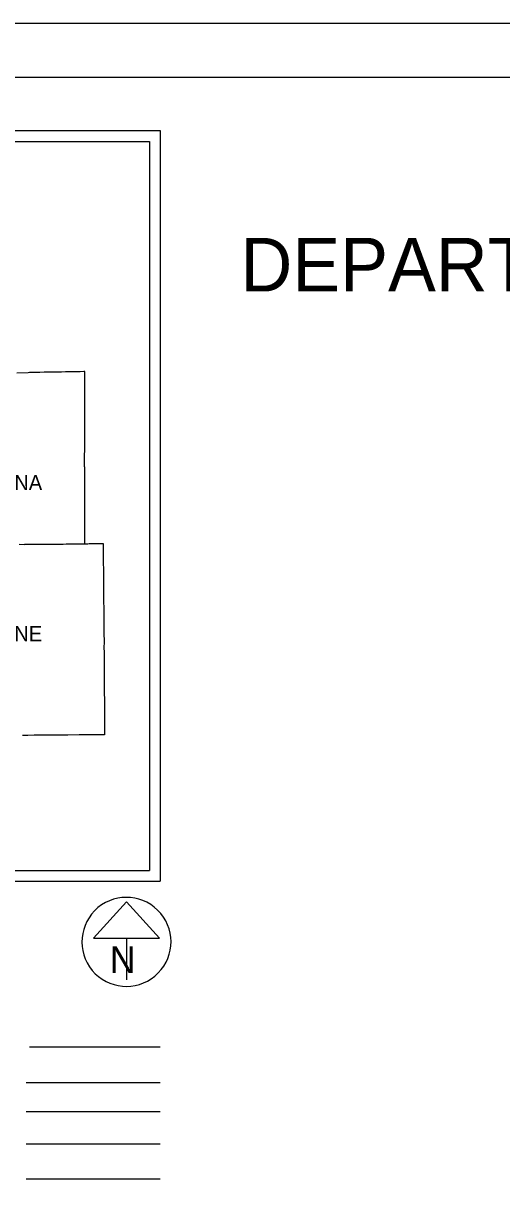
# Model space of a CAD drawing. Extents: x 0 to 34, y 0 to 22.
# Drawn here: x 7.72 to 12.18, y 11.1 to 22 of the extents above; entities that cross this region are included whole.
import ezdxf

# ---------------------------------------------------------------- set-up
doc = ezdxf.new("R2010")
doc.units = 0
for name, color, linetype in [('Default', 7, 'Continuous'), ('SH_Border', 7, 'Continuous'), ('SH_Cut_Line', 7, 'Continuous'), ('SH_Data', 7, 'Continuous'), ('SH_Text', 7, 'Continuous')]:
    doc.layers.add(name, color=color, linetype=linetype)

msp = doc.modelspace()

# ---------------------------------------------------------------- linework, layer by layer
at = {"layer": 'Default'}
for points in [[(7.687, 17.143), (7.733, 17.142), (7.738, 17.143), (7.761, 17.143), (7.842, 17.143), (7.849, 17.143), (7.887, 17.143), (7.908, 17.143), (7.944, 17.143), (7.967, 17.143), (7.975, 17.143), (7.998, 17.144), (8.025, 17.144), (8.044, 17.145), (8.094, 17.145), (8.122, 17.146), (8.152, 17.146), (8.183, 17.147), (8.209, 17.147), (8.223, 17.148), (8.231, 17.148), (8.265, 17.148), (8.297, 17.148), (8.297, 17.185), (8.297, 17.192), (8.297, 17.216), (8.297, 17.235), (8.297, 17.244), (8.296, 17.296), (8.298, 17.355), (8.297, 17.425), (8.297, 17.429), (8.297, 17.435), (8.297, 17.438), (8.297, 17.442), (8.297, 17.445), (8.297, 17.457), (8.297, 17.459), (8.297, 17.47), (8.297, 17.485), (8.297, 17.49), (8.297, 17.498), (8.296, 17.518), (8.296, 17.547), (8.296, 17.553), (8.296, 17.558), (8.296, 17.563), (8.296, 17.602), (8.296, 17.611), (8.296, 17.662), (8.296, 17.663), (8.296, 17.715), (8.296, 17.73), (8.296, 17.764), (8.296, 17.804), (8.296, 17.853), (8.296, 17.857), (8.295, 17.867), (8.295, 17.879), (8.295, 17.924), (8.295, 17.968), (8.296, 18.026), (8.296, 18.049), (8.296, 18.052), (8.296, 18.061), (8.296, 18.078), (8.296, 18.106), (8.296, 18.113), (8.296, 18.117), (8.296, 18.133), (8.296, 18.149), (8.296, 18.199), (8.296, 18.259), (8.297, 18.328), (8.297, 18.336), (8.297, 18.38), (8.297, 18.43), (8.297, 18.46), (8.297, 18.545), (8.297, 18.6), (8.297, 18.645), (8.297, 18.662), (8.297, 18.719), (8.297, 18.72), (8.297, 18.753), (8.289, 18.753), (8.253, 18.752), (8.23, 18.752), (8.154, 18.751), (8.151, 18.751), (8.149, 18.751), (8.148, 18.751), (8.148, 18.75), (8.117, 18.75), (8.08, 18.749), (8.046, 18.749), (8.016, 18.748), (7.991, 18.748), (7.985, 18.748), (7.938, 18.747), (7.918, 18.746), (7.877, 18.745), (7.84, 18.745), (7.832, 18.745), (7.824, 18.745), (7.821, 18.744), (7.787, 18.743), (7.781, 18.743), (7.769, 18.742), (7.663, 18.739)], [(7.687, 17.143), (7.733, 17.142), (7.738, 17.143), (7.761, 17.143), (7.842, 17.143), (7.849, 17.143), (7.887, 17.143), (7.908, 17.143), (7.944, 17.143), (7.967, 17.143), (7.975, 17.143), (7.998, 17.144), (8.025, 17.144), (8.044, 17.145), (8.094, 17.145), (8.122, 17.146), (8.152, 17.146), (8.183, 17.147), (8.209, 17.147), (8.223, 17.148), (8.231, 17.148), (8.265, 17.148), (8.297, 17.148), (8.307, 17.148), (8.326, 17.148), (8.337, 17.149), (8.339, 17.149), (8.365, 17.149), (8.376, 17.149), (8.382, 17.149), (8.388, 17.149), (8.402, 17.149), (8.405, 17.149), (8.46, 17.15), (8.468, 17.15), (8.468, 17.143), (8.469, 17.104), (8.469, 17.097), (8.469, 17.09), (8.469, 17.079), (8.469, 17.064), (8.469, 17.048), (8.469, 16.994), (8.469, 16.98), (8.47, 16.898), (8.47, 16.865), (8.471, 16.818), (8.471, 16.817), (8.471, 16.755), (8.471, 16.736), (8.472, 16.727), (8.472, 16.694), (8.472, 16.684), (8.472, 16.671), (8.472, 16.67), (8.472, 16.629), (8.473, 16.528), (8.473, 16.491), (8.474, 16.401), (8.474, 16.326), (8.474, 16.304), (8.476, 16.245), (8.476, 16.23), (8.475, 16.181), (8.476, 16.132), (8.476, 16.129), (8.476, 16.128), (8.476, 16.123), (8.476, 16.113), (8.476, 16.098), (8.476, 16.093), (8.476, 16.082), (8.477, 16.059), (8.476, 15.977), (8.476, 15.97), (8.477, 15.896), (8.477, 15.875), (8.478, 15.814), (8.478, 15.75), (8.478, 15.739), (8.479, 15.712), (8.479, 15.69), (8.48, 15.592), (8.48, 15.56), (8.48, 15.487), (8.48, 15.366), (8.48, 15.365), (8.411, 15.365), (8.315, 15.365), (8.245, 15.365), (8.138, 15.364), (8.093, 15.363), (8.069, 15.362), (8.041, 15.362), (8.003, 15.361), (7.988, 15.361), (7.947, 15.361), (7.907, 15.361), (7.825, 15.361), (7.765, 15.36), (7.718, 15.359)]]:
    msp.add_lwpolyline(points, dxfattribs=at)
at = {"layer": 'SH_Border'}
msp.add_lwpolyline([(1.5, 21.5), (33.5, 21.5), (33.5, 0.5), (1.5, 0.5)], close=True, dxfattribs=at)
at = {"layer": 'SH_Cut_Line'}
msp.add_lwpolyline([(0, 0), (34, 0), (34, 22), (0, 22)], close=True, dxfattribs=at)
at = {"layer": 'SH_Data'}
for p, q in [((2, 21), (9, 21)), ((9, 21), (9, 14)), ((2.1, 20.9), (8.9, 20.9)), ((8.9, 20.9), (8.9, 14.1)), ((2.1, 14.1), (8.9, 14.1)), ((2, 14), (9, 14)), ((8.685, 13.809), (8.377, 13.468)), ((8.992, 13.468), (8.685, 13.809)), ((8.377, 13.468), (8.992, 13.468)), ((8.685, 13.468), (8.685, 13.081)), ((8.685, 13.435), (8.685, 13.435)), ((8.685, 13.435), (8.685, 13.435)), ((7.783, 12.455), (9, 12.455)), ((9, 12.121), (7.75, 12.121)), ((9, 11.849), (7.75, 11.849)), ((9, 11.549), (7.75, 11.549)), ((9, 11.222), (7.75, 11.222))]:
    msp.add_line(p, q, dxfattribs=at)
msp.add_arc((8.685, 13.435), 0.415, 129.7798, 129.7633, dxfattribs=at)

# ---------------------------------------------------------------- texts
at = {"layer": 'Default'}
for s, p in [('MEDINA', (7.172, 17.648)), ('WAYNE', (7.213, 16.239))]:
    msp.add_text(s, height=0.14, dxfattribs=at).set_placement(p)
at = {"layer": 'SH_Data'}
msp.add_text('N', height=0.25, dxfattribs=at).set_placement((8.529, 13.144))
at = {"layer": 'SH_Text'}
msp.add_text('DEPARTMENT OF TRANSPORTATION', height=0.5, dxfattribs=at).set_placement((9.747, 19.5))

doc.saveas('drawing.dxf')
